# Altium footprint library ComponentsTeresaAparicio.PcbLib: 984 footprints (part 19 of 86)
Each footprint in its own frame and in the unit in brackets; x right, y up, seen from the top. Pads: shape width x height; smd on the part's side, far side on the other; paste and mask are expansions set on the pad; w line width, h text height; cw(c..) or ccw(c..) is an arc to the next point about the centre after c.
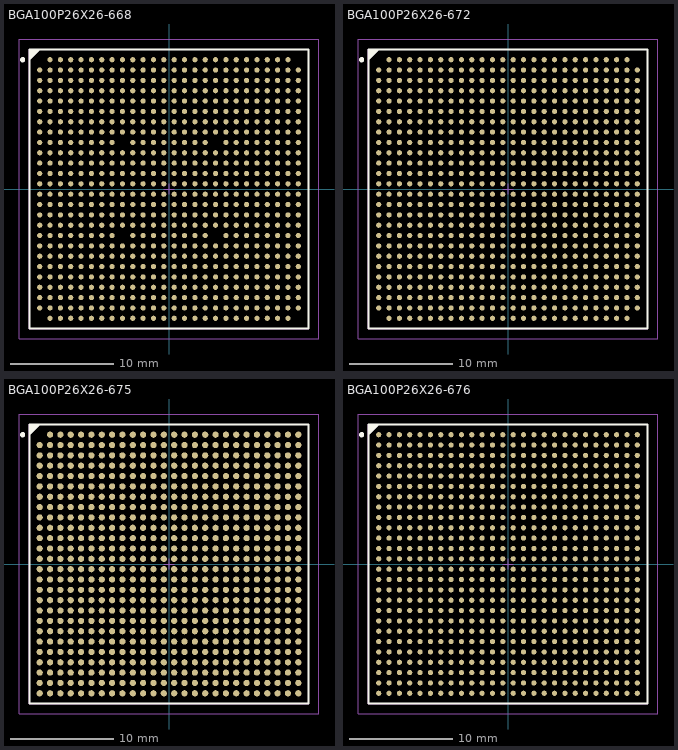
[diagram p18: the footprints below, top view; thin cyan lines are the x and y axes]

## BGA100P26X26-668 [mm] "668-Ball Flip Chip Fine Pitch Ball Grid Array (FF668)"
height 2.85
pads (668):
  round 0.5 smd: A2(-11.5,12.5) A3(-10.5,12.5) A4(-9.5,12.5) A5(-8.5,12.5) A6(-7.5,12.5) A7(-6.5,12.5) A8(-5.5,12.5) A9(-4.5,12.5) A10(-3.5,12.5) A11(-2.5,12.5) A12(-1.5,12.5) A13(-0.5,12.5) A14(0.5,12.5) A15(1.5,12.5) A16(2.5,12.5) A17(3.5,12.5) A18(4.5,12.5) A19(5.5,12.5) A20(6.5,12.5) A21(7.5,12.5) A22(8.5,12.5) A23(9.5,12.5) A24(10.5,12.5) A25(11.5,12.5) AA1(-12.5,-7.5) AA2(-11.5,-7.5) AA3(-10.5,-7.5) AA4(-9.5,-7.5) AA5(-8.5,-7.5) AA6(-7.5,-7.5) AA7(-6.5,-7.5) AA8(-5.5,-7.5) AA9(-4.5,-7.5) AA10(-3.5,-7.5) AA11(-2.5,-7.5) AA12(-1.5,-7.5) AA13(-0.5,-7.5) AA14(0.5,-7.5) AA15(1.5,-7.5) AA16(2.5,-7.5) AA17(3.5,-7.5) AA18(4.5,-7.5) AA19(5.5,-7.5) AA20(6.5,-7.5) AA21(7.5,-7.5) AA22(8.5,-7.5) AA23(9.5,-7.5) AA24(10.5,-7.5) AA25(11.5,-7.5) AA26(12.5,-7.5) AB1(-12.5,-8.5) AB2(-11.5,-8.5) AB3(-10.5,-8.5) AB4(-9.5,-8.5) AB5(-8.5,-8.5) AB6(-7.5,-8.5) AB7(-6.5,-8.5) AB8(-5.5,-8.5) AB9(-4.5,-8.5) AB10(-3.5,-8.5) AB11(-2.5,-8.5) AB12(-1.5,-8.5) AB13(-0.5,-8.5) AB14(0.5,-8.5) AB15(1.5,-8.5) AB16(2.5,-8.5) AB17(3.5,-8.5) AB18(4.5,-8.5) AB19(5.5,-8.5) AB20(6.5,-8.5) AB21(7.5,-8.5) AB22(8.5,-8.5) AB23(9.5,-8.5) AB24(10.5,-8.5) AB25(11.5,-8.5) AB26(12.5,-8.5) AC1(-12.5,-9.5) AC2(-11.5,-9.5) AC3(-10.5,-9.5) AC4(-9.5,-9.5) AC5(-8.5,-9.5) AC6(-7.5,-9.5) AC7(-6.5,-9.5) AC8(-5.5,-9.5) AC9(-4.5,-9.5) AC10(-3.5,-9.5) AC11(-2.5,-9.5) AC12(-1.5,-9.5) AC13(-0.5,-9.5) AC14(0.5,-9.5) AC15(1.5,-9.5) AC16(2.5,-9.5) AC17(3.5,-9.5) AC18(4.5,-9.5) AC19(5.5,-9.5) AC20(6.5,-9.5) AC21(7.5,-9.5) AC22(8.5,-9.5) AC23(9.5,-9.5) AC24(10.5,-9.5) AC25(11.5,-9.5) AC26(12.5,-9.5) AD1(-12.5,-10.5) AD2(-11.5,-10.5) AD3(-10.5,-10.5) AD4(-9.5,-10.5) AD5(-8.5,-10.5) AD6(-7.5,-10.5) AD7(-6.5,-10.5) AD8(-5.5,-10.5) AD9(-4.5,-10.5) AD10(-3.5,-10.5) AD11(-2.5,-10.5) AD12(-1.5,-10.5) AD13(-0.5,-10.5) AD14(0.5,-10.5) AD15(1.5,-10.5) AD16(2.5,-10.5) AD17(3.5,-10.5) AD18(4.5,-10.5) AD19(5.5,-10.5) AD20(6.5,-10.5) AD21(7.5,-10.5) AD22(8.5,-10.5) AD23(9.5,-10.5) AD24(10.5,-10.5) AD25(11.5,-10.5) AD26(12.5,-10.5) AE1(-12.5,-11.5) AE2(-11.5,-11.5) AE3(-10.5,-11.5) AE4(-9.5,-11.5) AE5(-8.5,-11.5) AE6(-7.5,-11.5) AE7(-6.5,-11.5) AE8(-5.5,-11.5) AE9(-4.5,-11.5) AE10(-3.5,-11.5) AE11(-2.5,-11.5) AE12(-1.5,-11.5) AE13(-0.5,-11.5) AE14(0.5,-11.5) AE15(1.5,-11.5) AE16(2.5,-11.5) AE17(3.5,-11.5) AE18(4.5,-11.5) AE19(5.5,-11.5) AE20(6.5,-11.5) AE21(7.5,-11.5) AE22(8.5,-11.5) AE23(9.5,-11.5) AE24(10.5,-11.5) AE25(11.5,-11.5) AE26(12.5,-11.5) AF2(-11.5,-12.5) AF3(-10.5,-12.5) AF4(-9.5,-12.5) AF5(-8.5,-12.5) AF6(-7.5,-12.5) AF7(-6.5,-12.5) AF8(-5.5,-12.5) AF9(-4.5,-12.5) AF10(-3.5,-12.5) AF11(-2.5,-12.5) AF12(-1.5,-12.5) AF13(-0.5,-12.5) AF14(0.5,-12.5) AF15(1.5,-12.5) AF16(2.5,-12.5) AF17(3.5,-12.5) AF18(4.5,-12.5) AF19(5.5,-12.5) AF20(6.5,-12.5) AF21(7.5,-12.5) AF22(8.5,-12.5) AF23(9.5,-12.5) AF24(10.5,-12.5) AF25(11.5,-12.5) B1(-12.5,11.5) B2(-11.5,11.5) B3(-10.5,11.5) B4(-9.5,11.5) B5(-8.5,11.5) B6(-7.5,11.5) B7(-6.5,11.5) B8(-5.5,11.5) B9(-4.5,11.5) B10(-3.5,11.5) B11(-2.5,11.5) B12(-1.5,11.5) B13(-0.5,11.5) B14(0.5,11.5) B15(1.5,11.5) B16(2.5,11.5) B17(3.5,11.5) B18(4.5,11.5) B19(5.5,11.5) B20(6.5,11.5) B21(7.5,11.5) B22(8.5,11.5) B23(9.5,11.5) B24(10.5,11.5) B25(11.5,11.5) B26(12.5,11.5) C1(-12.5,10.5) C2(-11.5,10.5) C3(-10.5,10.5) C4(-9.5,10.5) C5(-8.5,10.5) C6(-7.5,10.5) C7(-6.5,10.5) C8(-5.5,10.5) C9(-4.5,10.5) C10(-3.5,10.5) C11(-2.5,10.5) C12(-1.5,10.5) C13(-0.5,10.5) C14(0.5,10.5) C15(1.5,10.5) C16(2.5,10.5) C17(3.5,10.5) C18(4.5,10.5) C19(5.5,10.5) C20(6.5,10.5) C21(7.5,10.5) C22(8.5,10.5) C23(9.5,10.5) C24(10.5,10.5) C25(11.5,10.5) C26(12.5,10.5) D1(-12.5,9.5) D2(-11.5,9.5) D3(-10.5,9.5) D4(-9.5,9.5) D5(-8.5,9.5) D6(-7.5,9.5) D7(-6.5,9.5) D8(-5.5,9.5) D9(-4.5,9.5) D10(-3.5,9.5) D11(-2.5,9.5) D12(-1.5,9.5) D13(-0.5,9.5) D14(0.5,9.5) D15(1.5,9.5) D16(2.5,9.5) D17(3.5,9.5) D18(4.5,9.5) D19(5.5,9.5) D20(6.5,9.5) D21(7.5,9.5) D22(8.5,9.5) D23(9.5,9.5) D24(10.5,9.5) D25(11.5,9.5) D26(12.5,9.5) E1(-12.5,8.5) E2(-11.5,8.5) E3(-10.5,8.5) E4(-9.5,8.5) E5(-8.5,8.5) E6(-7.5,8.5) E7(-6.5,8.5) E8(-5.5,8.5) E9(-4.5,8.5) E10(-3.5,8.5) E11(-2.5,8.5) E12(-1.5,8.5) E13(-0.5,8.5) E14(0.5,8.5) E15(1.5,8.5) E16(2.5,8.5) E17(3.5,8.5) E18(4.5,8.5) E19(5.5,8.5) E20(6.5,8.5) E21(7.5,8.5) E22(8.5,8.5) E23(9.5,8.5) E24(10.5,8.5) E25(11.5,8.5) E26(12.5,8.5) F1(-12.5,7.5) F2(-11.5,7.5) F3(-10.5,7.5) F4(-9.5,7.5) F5(-8.5,7.5) F6(-7.5,7.5) F7(-6.5,7.5) F8(-5.5,7.5) F9(-4.5,7.5) F10(-3.5,7.5) F11(-2.5,7.5) F12(-1.5,7.5) F13(-0.5,7.5) F14(0.5,7.5) F15(1.5,7.5) F16(2.5,7.5) F17(3.5,7.5) F18(4.5,7.5) F19(5.5,7.5) F20(6.5,7.5) F21(7.5,7.5) F22(8.5,7.5) F23(9.5,7.5) F24(10.5,7.5) F25(11.5,7.5) F26(12.5,7.5) G1(-12.5,6.5) G2(-11.5,6.5) G3(-10.5,6.5) G4(-9.5,6.5) G5(-8.5,6.5) G6(-7.5,6.5) G7(-6.5,6.5) G8(-5.5,6.5) G9(-4.5,6.5) G10(-3.5,6.5) G11(-2.5,6.5) G12(-1.5,6.5) G13(-0.5,6.5) G14(0.5,6.5) G15(1.5,6.5) G16(2.5,6.5) G17(3.5,6.5) G18(4.5,6.5) G19(5.5,6.5) G20(6.5,6.5) G21(7.5,6.5) G22(8.5,6.5) G23(9.5,6.5) G24(10.5,6.5) G25(11.5,6.5) G26(12.5,6.5) H1(-12.5,5.5) H2(-11.5,5.5) H3(-10.5,5.5) H4(-9.5,5.5) H5(-8.5,5.5) H6(-7.5,5.5) H7(-6.5,5.5) H8(-5.5,5.5) H9(-4.5,5.5) H10(-3.5,5.5) H11(-2.5,5.5) H12(-1.5,5.5) H13(-0.5,5.5) H14(0.5,5.5) H15(1.5,5.5) H16(2.5,5.5) H17(3.5,5.5) H18(4.5,5.5) H19(5.5,5.5) H20(6.5,5.5) H21(7.5,5.5) H22(8.5,5.5) H23(9.5,5.5) H24(10.5,5.5) H25(11.5,5.5) H26(12.5,5.5) J1(-12.5,4.5) J2(-11.5,4.5) J3(-10.5,4.5) J4(-9.5,4.5) J5(-8.5,4.5) J6(-7.5,4.5) J7(-6.5,4.5) J8(-5.5,4.5) J10(-3.5,4.5) J11(-2.5,4.5) J12(-1.5,4.5) J13(-0.5,4.5) J14(0.5,4.5) J15(1.5,4.5) J16(2.5,4.5) J17(3.5,4.5) J19(5.5,4.5) J20(6.5,4.5) J21(7.5,4.5) J22(8.5,4.5) J23(9.5,4.5) J24(10.5,4.5) J25(11.5,4.5) J26(12.5,4.5) K1(-12.5,3.5) K2(-11.5,3.5) K3(-10.5,3.5) K4(-9.5,3.5) K5(-8.5,3.5) K6(-7.5,3.5) K7(-6.5,3.5) K8(-5.5,3.5) K9(-4.5,3.5) K10(-3.5,3.5) K11(-2.5,3.5) K12(-1.5,3.5) K13(-0.5,3.5) K14(0.5,3.5) K15(1.5,3.5) K16(2.5,3.5) K17(3.5,3.5) K18(4.5,3.5) K19(5.5,3.5) K20(6.5,3.5) K21(7.5,3.5) K22(8.5,3.5) K23(9.5,3.5) K24(10.5,3.5) K25(11.5,3.5) K26(12.5,3.5) L1(-12.5,2.5) L2(-11.5,2.5) L3(-10.5,2.5) L4(-9.5,2.5) L5(-8.5,2.5) L6(-7.5,2.5) L7(-6.5,2.5) L8(-5.5,2.5) L9(-4.5,2.5) L10(-3.5,2.5) L11(-2.5,2.5) L12(-1.5,2.5) L13(-0.5,2.5) L14(0.5,2.5) L15(1.5,2.5) L16(2.5,2.5) L17(3.5,2.5) L18(4.5,2.5) L19(5.5,2.5) L20(6.5,2.5) L21(7.5,2.5) L22(8.5,2.5) L23(9.5,2.5) L24(10.5,2.5) L25(11.5,2.5) L26(12.5,2.5) M1(-12.5,1.5) M2(-11.5,1.5) M3(-10.5,1.5) M4(-9.5,1.5) M5(-8.5,1.5) M6(-7.5,1.5) M7(-6.5,1.5) M8(-5.5,1.5) M9(-4.5,1.5) M10(-3.5,1.5) M11(-2.5,1.5) M12(-1.5,1.5) M13(-0.5,1.5) M14(0.5,1.5) M15(1.5,1.5) M16(2.5,1.5) M17(3.5,1.5) M18(4.5,1.5) M19(5.5,1.5) M20(6.5,1.5) M21(7.5,1.5) M22(8.5,1.5) M23(9.5,1.5) M24(10.5,1.5) M25(11.5,1.5) M26(12.5,1.5) N1(-12.5,0.5) N2(-11.5,0.5) N3(-10.5,0.5) N4(-9.5,0.5) N5(-8.5,0.5) N6(-7.5,0.5) N7(-6.5,0.5) N8(-5.5,0.5) N9(-4.5,0.5) N10(-3.5,0.5) N11(-2.5,0.5) N12(-1.5,0.5) N13(-0.5,0.5) N14(0.5,0.5) N15(1.5,0.5) N16(2.5,0.5) N17(3.5,0.5) N18(4.5,0.5) N19(5.5,0.5) N20(6.5,0.5) N21(7.5,0.5) N22(8.5,0.5) N23(9.5,0.5) N24(10.5,0.5) N25(11.5,0.5) N26(12.5,0.5) P1(-12.5,-0.5) P2(-11.5,-0.5) P3(-10.5,-0.5) P4(-9.5,-0.5) P5(-8.5,-0.5) P6(-7.5,-0.5) P7(-6.5,-0.5) P8(-5.5,-0.5) P9(-4.5,-0.5) P10(-3.5,-0.5) P11(-2.5,-0.5) P12(-1.5,-0.5) P13(-0.5,-0.5) P14(0.5,-0.5) P15(1.5,-0.5) P16(2.5,-0.5) P17(3.5,-0.5) P18(4.5,-0.5) P19(5.5,-0.5) P20(6.5,-0.5) P21(7.5,-0.5) P22(8.5,-0.5) P23(9.5,-0.5) P24(10.5,-0.5) P25(11.5,-0.5) P26(12.5,-0.5) R1(-12.5,-1.5) R2(-11.5,-1.5) R3(-10.5,-1.5) R4(-9.5,-1.5) R5(-8.5,-1.5) R6(-7.5,-1.5) R7(-6.5,-1.5) R8(-5.5,-1.5) R9(-4.5,-1.5) R10(-3.5,-1.5) R11(-2.5,-1.5) R12(-1.5,-1.5) R13(-0.5,-1.5) R14(0.5,-1.5) R15(1.5,-1.5) R16(2.5,-1.5) R17(3.5,-1.5) R18(4.5,-1.5) R19(5.5,-1.5) R20(6.5,-1.5) R21(7.5,-1.5) R22(8.5,-1.5) R23(9.5,-1.5) R24(10.5,-1.5) R25(11.5,-1.5) R26(12.5,-1.5) T1(-12.5,-2.5) T2(-11.5,-2.5) T3(-10.5,-2.5) T4(-9.5,-2.5) T5(-8.5,-2.5) T6(-7.5,-2.5) T7(-6.5,-2.5) T8(-5.5,-2.5) T9(-4.5,-2.5) T10(-3.5,-2.5) T11(-2.5,-2.5) T12(-1.5,-2.5) T13(-0.5,-2.5) T14(0.5,-2.5) T15(1.5,-2.5) T16(2.5,-2.5) T17(3.5,-2.5) T18(4.5,-2.5) T19(5.5,-2.5) T20(6.5,-2.5) T21(7.5,-2.5) T22(8.5,-2.5) T23(9.5,-2.5) T24(10.5,-2.5) T25(11.5,-2.5) T26(12.5,-2.5) U1(-12.5,-3.5) U2(-11.5,-3.5) U3(-10.5,-3.5) U4(-9.5,-3.5) U5(-8.5,-3.5) U6(-7.5,-3.5) U7(-6.5,-3.5) U8(-5.5,-3.5) U9(-4.5,-3.5) U10(-3.5,-3.5) U11(-2.5,-3.5) U12(-1.5,-3.5) U13(-0.5,-3.5) U14(0.5,-3.5) U15(1.5,-3.5) U16(2.5,-3.5) U17(3.5,-3.5) U18(4.5,-3.5) U19(5.5,-3.5) U20(6.5,-3.5) U21(7.5,-3.5) U22(8.5,-3.5) U23(9.5,-3.5) U24(10.5,-3.5) U25(11.5,-3.5) U26(12.5,-3.5) V1(-12.5,-4.5) V2(-11.5,-4.5) V3(-10.5,-4.5) V4(-9.5,-4.5) V5(-8.5,-4.5) V6(-7.5,-4.5) V7(-6.5,-4.5) V8(-5.5,-4.5) V10(-3.5,-4.5) V11(-2.5,-4.5) V12(-1.5,-4.5) V13(-0.5,-4.5) V14(0.5,-4.5) V15(1.5,-4.5) V16(2.5,-4.5) V17(3.5,-4.5) V19(5.5,-4.5) V20(6.5,-4.5) V21(7.5,-4.5) V22(8.5,-4.5) V23(9.5,-4.5) V24(10.5,-4.5) V25(11.5,-4.5) V26(12.5,-4.5) W1(-12.5,-5.5) W2(-11.5,-5.5) W3(-10.5,-5.5) W4(-9.5,-5.5) W5(-8.5,-5.5) W6(-7.5,-5.5) W7(-6.5,-5.5) W8(-5.5,-5.5) W9(-4.5,-5.5) W10(-3.5,-5.5) W11(-2.5,-5.5) W12(-1.5,-5.5) W13(-0.5,-5.5) W14(0.5,-5.5) W15(1.5,-5.5) W16(2.5,-5.5) W17(3.5,-5.5) W18(4.5,-5.5) W19(5.5,-5.5) W20(6.5,-5.5) W21(7.5,-5.5) W22(8.5,-5.5) W23(9.5,-5.5) W24(10.5,-5.5) W25(11.5,-5.5) W26(12.5,-5.5) Y1(-12.5,-6.5) Y2(-11.5,-6.5) Y3(-10.5,-6.5) Y4(-9.5,-6.5) Y5(-8.5,-6.5) Y6(-7.5,-6.5) Y7(-6.5,-6.5) Y8(-5.5,-6.5) Y9(-4.5,-6.5) Y10(-3.5,-6.5) Y11(-2.5,-6.5) Y12(-1.5,-6.5) Y13(-0.5,-6.5) Y14(0.5,-6.5) Y15(1.5,-6.5) Y16(2.5,-6.5) Y17(3.5,-6.5) Y18(4.5,-6.5) Y19(5.5,-6.5) Y20(6.5,-6.5) Y21(7.5,-6.5) Y22(8.5,-6.5) Y23(9.5,-6.5) Y24(10.5,-6.5) Y25(11.5,-6.5) Y26(12.5,-6.5)
Top Overlay:
  circle w0.25: c-14.15,12.5 r0.125
  region: -12.5,13.5 -13.5,12.5 -13.5,13.5
  lines w0.2: -13.5,12.5 -12.5,13.5 ; -13.5,-13.5 13.5,-13.5 13.5,13.5 -13.5,13.5 -13.5,-13.5
Mechanical 13:
  lines w0.1: -13.5,-13.5 13.5,-13.5 13.5,13.5 -13.5,13.5 -13.5,-13.5
Mechanical 15:
  lines w0.1: -0.5,0 0.5,0 ; 0,-0.5 0,0.5 ; -14.5,-14.5 14.5,-14.5 14.5,14.5 -14.5,14.5 -14.5,-14.5
3D body: height 0, standoff 0, extent -13.5,-13.5 13.5,13.5

## BGA100P26X26-672 [mm] "BGA, 672-Leads, Body 27x27mm, Pitch 1mm"
height 3.5
pads (672):
  round 0.5 smd: A2(-11.5,12.5) A3(-10.5,12.5) A4(-9.5,12.5) A5(-8.5,12.5) A6(-7.5,12.5) A7(-6.5,12.5) A8(-5.5,12.5) A9(-4.5,12.5) A10(-3.5,12.5) A11(-2.5,12.5) A12(-1.5,12.5) A13(-0.5,12.5) A14(0.5,12.5) A15(1.5,12.5) A16(2.5,12.5) A17(3.5,12.5) A18(4.5,12.5) A19(5.5,12.5) A20(6.5,12.5) A21(7.5,12.5) A22(8.5,12.5) A23(9.5,12.5) A24(10.5,12.5) A25(11.5,12.5) AA1(-12.5,-7.5) AA2(-11.5,-7.5) AA3(-10.5,-7.5) AA4(-9.5,-7.5) AA5(-8.5,-7.5) AA6(-7.5,-7.5) AA7(-6.5,-7.5) AA8(-5.5,-7.5) AA9(-4.5,-7.5) AA10(-3.5,-7.5) AA11(-2.5,-7.5) AA12(-1.5,-7.5) AA13(-0.5,-7.5) AA14(0.5,-7.5) AA15(1.5,-7.5) AA16(2.5,-7.5) AA17(3.5,-7.5) AA18(4.5,-7.5) AA19(5.5,-7.5) AA20(6.5,-7.5) AA21(7.5,-7.5) AA22(8.5,-7.5) AA23(9.5,-7.5) AA24(10.5,-7.5) AA25(11.5,-7.5) AA26(12.5,-7.5) AB1(-12.5,-8.5) AB2(-11.5,-8.5) AB3(-10.5,-8.5) AB4(-9.5,-8.5) AB5(-8.5,-8.5) AB6(-7.5,-8.5) AB7(-6.5,-8.5) AB8(-5.5,-8.5) AB9(-4.5,-8.5) AB10(-3.5,-8.5) AB11(-2.5,-8.5) AB12(-1.5,-8.5) AB13(-0.5,-8.5) AB14(0.5,-8.5) AB15(1.5,-8.5) AB16(2.5,-8.5) AB17(3.5,-8.5) AB18(4.5,-8.5) AB19(5.5,-8.5) AB20(6.5,-8.5) AB21(7.5,-8.5) AB22(8.5,-8.5) AB23(9.5,-8.5) AB24(10.5,-8.5) AB25(11.5,-8.5) AB26(12.5,-8.5) AC1(-12.5,-9.5) AC2(-11.5,-9.5) AC3(-10.5,-9.5) AC4(-9.5,-9.5) AC5(-8.5,-9.5) AC6(-7.5,-9.5) AC7(-6.5,-9.5) AC8(-5.5,-9.5) AC9(-4.5,-9.5) AC10(-3.5,-9.5) AC11(-2.5,-9.5) AC12(-1.5,-9.5) AC13(-0.5,-9.5) AC14(0.5,-9.5) AC15(1.5,-9.5) AC16(2.5,-9.5) AC17(3.5,-9.5) AC18(4.5,-9.5) AC19(5.5,-9.5) AC20(6.5,-9.5) AC21(7.5,-9.5) AC22(8.5,-9.5) AC23(9.5,-9.5) AC24(10.5,-9.5) AC25(11.5,-9.5) AC26(12.5,-9.5) AD1(-12.5,-10.5) AD2(-11.5,-10.5) AD3(-10.5,-10.5) AD4(-9.5,-10.5) AD5(-8.5,-10.5) AD6(-7.5,-10.5) AD7(-6.5,-10.5) AD8(-5.5,-10.5) AD9(-4.5,-10.5) AD10(-3.5,-10.5) AD11(-2.5,-10.5) AD12(-1.5,-10.5) AD13(-0.5,-10.5) AD14(0.5,-10.5) AD15(1.5,-10.5) AD16(2.5,-10.5) AD17(3.5,-10.5) AD18(4.5,-10.5) AD19(5.5,-10.5) AD20(6.5,-10.5) AD21(7.5,-10.5) AD22(8.5,-10.5) AD23(9.5,-10.5) AD24(10.5,-10.5) AD25(11.5,-10.5) AD26(12.5,-10.5) AE1(-12.5,-11.5) AE2(-11.5,-11.5) AE3(-10.5,-11.5) AE4(-9.5,-11.5) AE5(-8.5,-11.5) AE6(-7.5,-11.5) AE7(-6.5,-11.5) AE8(-5.5,-11.5) AE9(-4.5,-11.5) AE10(-3.5,-11.5) AE11(-2.5,-11.5) AE12(-1.5,-11.5) AE13(-0.5,-11.5) AE14(0.5,-11.5) AE15(1.5,-11.5) AE16(2.5,-11.5) AE17(3.5,-11.5) AE18(4.5,-11.5) AE19(5.5,-11.5) AE20(6.5,-11.5) AE21(7.5,-11.5) AE22(8.5,-11.5) AE23(9.5,-11.5) AE24(10.5,-11.5) AE25(11.5,-11.5) AE26(12.5,-11.5) AF2(-11.5,-12.5) AF3(-10.5,-12.5) AF4(-9.5,-12.5) AF5(-8.5,-12.5) AF6(-7.5,-12.5) AF7(-6.5,-12.5) AF8(-5.5,-12.5) AF9(-4.5,-12.5) AF10(-3.5,-12.5) AF11(-2.5,-12.5) AF12(-1.5,-12.5) AF13(-0.5,-12.5) AF14(0.5,-12.5) AF15(1.5,-12.5) AF16(2.5,-12.5) AF17(3.5,-12.5) AF18(4.5,-12.5) AF19(5.5,-12.5) AF20(6.5,-12.5) AF21(7.5,-12.5) AF22(8.5,-12.5) AF23(9.5,-12.5) AF24(10.5,-12.5) AF25(11.5,-12.5) B1(-12.5,11.5) B2(-11.5,11.5) B3(-10.5,11.5) B4(-9.5,11.5) B5(-8.5,11.5) B6(-7.5,11.5) B7(-6.5,11.5) B8(-5.5,11.5) B9(-4.5,11.5) B10(-3.5,11.5) B11(-2.5,11.5) B12(-1.5,11.5) B13(-0.5,11.5) B14(0.5,11.5) B15(1.5,11.5) B16(2.5,11.5) B17(3.5,11.5) B18(4.5,11.5) B19(5.5,11.5) B20(6.5,11.5) B21(7.5,11.5) B22(8.5,11.5) B23(9.5,11.5) B24(10.5,11.5) B25(11.5,11.5) B26(12.5,11.5) C1(-12.5,10.5) C2(-11.5,10.5) C3(-10.5,10.5) C4(-9.5,10.5) C5(-8.5,10.5) C6(-7.5,10.5) C7(-6.5,10.5) C8(-5.5,10.5) C9(-4.5,10.5) C10(-3.5,10.5) C11(-2.5,10.5) C12(-1.5,10.5) C13(-0.5,10.5) C14(0.5,10.5) C15(1.5,10.5) C16(2.5,10.5) C17(3.5,10.5) C18(4.5,10.5) C19(5.5,10.5) C20(6.5,10.5) C21(7.5,10.5) C22(8.5,10.5) C23(9.5,10.5) C24(10.5,10.5) C25(11.5,10.5) C26(12.5,10.5) D1(-12.5,9.5) D2(-11.5,9.5) D3(-10.5,9.5) D4(-9.5,9.5) D5(-8.5,9.5) D6(-7.5,9.5) D7(-6.5,9.5) D8(-5.5,9.5) D9(-4.5,9.5) D10(-3.5,9.5) D11(-2.5,9.5) D12(-1.5,9.5) D13(-0.5,9.5) D14(0.5,9.5) D15(1.5,9.5) D16(2.5,9.5) D17(3.5,9.5) D18(4.5,9.5) D19(5.5,9.5) D20(6.5,9.5) D21(7.5,9.5) D22(8.5,9.5) D23(9.5,9.5) D24(10.5,9.5) D25(11.5,9.5) D26(12.5,9.5) E1(-12.5,8.5) E2(-11.5,8.5) E3(-10.5,8.5) E4(-9.5,8.5) E5(-8.5,8.5) E6(-7.5,8.5) E7(-6.5,8.5) E8(-5.5,8.5) E9(-4.5,8.5) E10(-3.5,8.5) E11(-2.5,8.5) E12(-1.5,8.5) E13(-0.5,8.5) E14(0.5,8.5) E15(1.5,8.5) E16(2.5,8.5) E17(3.5,8.5) E18(4.5,8.5) E19(5.5,8.5) E20(6.5,8.5) E21(7.5,8.5) E22(8.5,8.5) E23(9.5,8.5) E24(10.5,8.5) E25(11.5,8.5) E26(12.5,8.5) F1(-12.5,7.5) F2(-11.5,7.5) F3(-10.5,7.5) F4(-9.5,7.5) F5(-8.5,7.5) F6(-7.5,7.5) F7(-6.5,7.5) F8(-5.5,7.5) F9(-4.5,7.5) F10(-3.5,7.5) F11(-2.5,7.5) F12(-1.5,7.5) F13(-0.5,7.5) F14(0.5,7.5) F15(1.5,7.5) F16(2.5,7.5) F17(3.5,7.5) F18(4.5,7.5) F19(5.5,7.5) F20(6.5,7.5) F21(7.5,7.5) F22(8.5,7.5) F23(9.5,7.5) F24(10.5,7.5) F25(11.5,7.5) F26(12.5,7.5) G1(-12.5,6.5) G2(-11.5,6.5) G3(-10.5,6.5) G4(-9.5,6.5) G5(-8.5,6.5) G6(-7.5,6.5) G7(-6.5,6.5) G8(-5.5,6.5) G9(-4.5,6.5) G10(-3.5,6.5) G11(-2.5,6.5) G12(-1.5,6.5) G13(-0.5,6.5) G14(0.5,6.5) G15(1.5,6.5) G16(2.5,6.5) G17(3.5,6.5) G18(4.5,6.5) G19(5.5,6.5) G20(6.5,6.5) G21(7.5,6.5) G22(8.5,6.5) G23(9.5,6.5) G24(10.5,6.5) G25(11.5,6.5) G26(12.5,6.5) H1(-12.5,5.5) H2(-11.5,5.5) H3(-10.5,5.5) H4(-9.5,5.5) H5(-8.5,5.5) H6(-7.5,5.5) H7(-6.5,5.5) H8(-5.5,5.5) H9(-4.5,5.5) H10(-3.5,5.5) H11(-2.5,5.5) H12(-1.5,5.5) H13(-0.5,5.5) H14(0.5,5.5) H15(1.5,5.5) H16(2.5,5.5) H17(3.5,5.5) H18(4.5,5.5) H19(5.5,5.5) H20(6.5,5.5) H21(7.5,5.5) H22(8.5,5.5) H23(9.5,5.5) H24(10.5,5.5) H25(11.5,5.5) H26(12.5,5.5) J1(-12.5,4.5) J2(-11.5,4.5) J3(-10.5,4.5) J4(-9.5,4.5) J5(-8.5,4.5) J6(-7.5,4.5) J7(-6.5,4.5) J8(-5.5,4.5) J9(-4.5,4.5) J10(-3.5,4.5) J11(-2.5,4.5) J12(-1.5,4.5) J13(-0.5,4.5) J14(0.5,4.5) J15(1.5,4.5) J16(2.5,4.5) J17(3.5,4.5) J18(4.5,4.5) J19(5.5,4.5) J20(6.5,4.5) J21(7.5,4.5) J22(8.5,4.5) J23(9.5,4.5) J24(10.5,4.5) J25(11.5,4.5) J26(12.5,4.5) K1(-12.5,3.5) K2(-11.5,3.5) K3(-10.5,3.5) K4(-9.5,3.5) K5(-8.5,3.5) K6(-7.5,3.5) K7(-6.5,3.5) K8(-5.5,3.5) K9(-4.5,3.5) K10(-3.5,3.5) K11(-2.5,3.5) K12(-1.5,3.5) K13(-0.5,3.5) K14(0.5,3.5) K15(1.5,3.5) K16(2.5,3.5) K17(3.5,3.5) K18(4.5,3.5) K19(5.5,3.5) K20(6.5,3.5) K21(7.5,3.5) K22(8.5,3.5) K23(9.5,3.5) K24(10.5,3.5) K25(11.5,3.5) K26(12.5,3.5) L1(-12.5,2.5) L2(-11.5,2.5) L3(-10.5,2.5) L4(-9.5,2.5) L5(-8.5,2.5) L6(-7.5,2.5) L7(-6.5,2.5) L8(-5.5,2.5) L9(-4.5,2.5) L10(-3.5,2.5) L11(-2.5,2.5) L12(-1.5,2.5) L13(-0.5,2.5) L14(0.5,2.5) L15(1.5,2.5) L16(2.5,2.5) L17(3.5,2.5) L18(4.5,2.5) L19(5.5,2.5) L20(6.5,2.5) L21(7.5,2.5) L22(8.5,2.5) L23(9.5,2.5) L24(10.5,2.5) L25(11.5,2.5) L26(12.5,2.5) M1(-12.5,1.5) M2(-11.5,1.5) M3(-10.5,1.5) M4(-9.5,1.5) M5(-8.5,1.5) M6(-7.5,1.5) M7(-6.5,1.5) M8(-5.5,1.5) M9(-4.5,1.5) M10(-3.5,1.5) M11(-2.5,1.5) M12(-1.5,1.5) M13(-0.5,1.5) M14(0.5,1.5) M15(1.5,1.5) M16(2.5,1.5) M17(3.5,1.5) M18(4.5,1.5) M19(5.5,1.5) M20(6.5,1.5) M21(7.5,1.5) M22(8.5,1.5) M23(9.5,1.5) M24(10.5,1.5) M25(11.5,1.5) M26(12.5,1.5) N1(-12.5,0.5) N2(-11.5,0.5) N3(-10.5,0.5) N4(-9.5,0.5) N5(-8.5,0.5) N6(-7.5,0.5) N7(-6.5,0.5) N8(-5.5,0.5) N9(-4.5,0.5) N10(-3.5,0.5) N11(-2.5,0.5) N12(-1.5,0.5) N13(-0.5,0.5) N14(0.5,0.5) N15(1.5,0.5) N16(2.5,0.5) N17(3.5,0.5) N18(4.5,0.5) N19(5.5,0.5) N20(6.5,0.5) N21(7.5,0.5) N22(8.5,0.5) N23(9.5,0.5) N24(10.5,0.5) N25(11.5,0.5) N26(12.5,0.5) P1(-12.5,-0.5) P2(-11.5,-0.5) P3(-10.5,-0.5) P4(-9.5,-0.5) P5(-8.5,-0.5) P6(-7.5,-0.5) P7(-6.5,-0.5) P8(-5.5,-0.5) P9(-4.5,-0.5) P10(-3.5,-0.5) P11(-2.5,-0.5) P12(-1.5,-0.5) P13(-0.5,-0.5) P14(0.5,-0.5) P15(1.5,-0.5) P16(2.5,-0.5) P17(3.5,-0.5) P18(4.5,-0.5) P19(5.5,-0.5) P20(6.5,-0.5) P21(7.5,-0.5) P22(8.5,-0.5) P23(9.5,-0.5) P24(10.5,-0.5) P25(11.5,-0.5) P26(12.5,-0.5) R1(-12.5,-1.5) R2(-11.5,-1.5) R3(-10.5,-1.5) R4(-9.5,-1.5) R5(-8.5,-1.5) R6(-7.5,-1.5) R7(-6.5,-1.5) R8(-5.5,-1.5) R9(-4.5,-1.5) R10(-3.5,-1.5) R11(-2.5,-1.5) R12(-1.5,-1.5) R13(-0.5,-1.5) R14(0.5,-1.5) R15(1.5,-1.5) R16(2.5,-1.5) R17(3.5,-1.5) R18(4.5,-1.5) R19(5.5,-1.5) R20(6.5,-1.5) R21(7.5,-1.5) R22(8.5,-1.5) R23(9.5,-1.5) R24(10.5,-1.5) R25(11.5,-1.5) R26(12.5,-1.5) T1(-12.5,-2.5) T2(-11.5,-2.5) T3(-10.5,-2.5) T4(-9.5,-2.5) T5(-8.5,-2.5) T6(-7.5,-2.5) T7(-6.5,-2.5) T8(-5.5,-2.5) T9(-4.5,-2.5) T10(-3.5,-2.5) T11(-2.5,-2.5) T12(-1.5,-2.5) T13(-0.5,-2.5) T14(0.5,-2.5) T15(1.5,-2.5) T16(2.5,-2.5) T17(3.5,-2.5) T18(4.5,-2.5) T19(5.5,-2.5) T20(6.5,-2.5) T21(7.5,-2.5) T22(8.5,-2.5) T23(9.5,-2.5) T24(10.5,-2.5) T25(11.5,-2.5) T26(12.5,-2.5) U1(-12.5,-3.5) U2(-11.5,-3.5) U3(-10.5,-3.5) U4(-9.5,-3.5) U5(-8.5,-3.5) U6(-7.5,-3.5) U7(-6.5,-3.5) U8(-5.5,-3.5) U9(-4.5,-3.5) U10(-3.5,-3.5) U11(-2.5,-3.5) U12(-1.5,-3.5) U13(-0.5,-3.5) U14(0.5,-3.5) U15(1.5,-3.5) U16(2.5,-3.5) U17(3.5,-3.5) U18(4.5,-3.5) U19(5.5,-3.5) U20(6.5,-3.5) U21(7.5,-3.5) U22(8.5,-3.5) U23(9.5,-3.5) U24(10.5,-3.5) U25(11.5,-3.5) U26(12.5,-3.5) V1(-12.5,-4.5) V2(-11.5,-4.5) V3(-10.5,-4.5) V4(-9.5,-4.5) V5(-8.5,-4.5) V6(-7.5,-4.5) V7(-6.5,-4.5) V8(-5.5,-4.5) V9(-4.5,-4.5) V10(-3.5,-4.5) V11(-2.5,-4.5) V12(-1.5,-4.5) V13(-0.5,-4.5) V14(0.5,-4.5) V15(1.5,-4.5) V16(2.5,-4.5) V17(3.5,-4.5) V18(4.5,-4.5) V19(5.5,-4.5) V20(6.5,-4.5) V21(7.5,-4.5) V22(8.5,-4.5) V23(9.5,-4.5) V24(10.5,-4.5) V25(11.5,-4.5) V26(12.5,-4.5) W1(-12.5,-5.5) W2(-11.5,-5.5) W3(-10.5,-5.5) W4(-9.5,-5.5) W5(-8.5,-5.5) W6(-7.5,-5.5) W7(-6.5,-5.5) W8(-5.5,-5.5) W9(-4.5,-5.5) W10(-3.5,-5.5) W11(-2.5,-5.5) W12(-1.5,-5.5) W13(-0.5,-5.5) W14(0.5,-5.5) W15(1.5,-5.5) W16(2.5,-5.5) W17(3.5,-5.5) W18(4.5,-5.5) W19(5.5,-5.5) W20(6.5,-5.5) W21(7.5,-5.5) W22(8.5,-5.5) W23(9.5,-5.5) W24(10.5,-5.5) W25(11.5,-5.5) W26(12.5,-5.5) Y1(-12.5,-6.5) Y2(-11.5,-6.5) Y3(-10.5,-6.5) Y4(-9.5,-6.5) Y5(-8.5,-6.5) Y6(-7.5,-6.5) Y7(-6.5,-6.5) Y8(-5.5,-6.5) Y9(-4.5,-6.5) Y10(-3.5,-6.5) Y11(-2.5,-6.5) Y12(-1.5,-6.5) Y13(-0.5,-6.5) Y14(0.5,-6.5) Y15(1.5,-6.5) Y16(2.5,-6.5) Y17(3.5,-6.5) Y18(4.5,-6.5) Y19(5.5,-6.5) Y20(6.5,-6.5) Y21(7.5,-6.5) Y22(8.5,-6.5) Y23(9.5,-6.5) Y24(10.5,-6.5) Y25(11.5,-6.5) Y26(12.5,-6.5)
Top Overlay:
  circle w0.25: c-14.15,12.5 r0.125
  region: -12.5,13.5 -13.5,12.5 -13.5,13.5
  lines w0.2: -13.5,12.5 -12.5,13.5 ; -13.5,-13.5 13.5,-13.5 13.5,13.5 -13.5,13.5 -13.5,-13.5
Mechanical 13:
  lines w0.1: -13.5,-13.5 13.5,-13.5 13.5,13.5 -13.5,13.5 -13.5,-13.5
Mechanical 15:
  lines w0.1: -0.5,0 0.5,0 ; 0,-0.5 0,0.5 ; -14.5,-14.5 14.5,-14.5 14.5,14.5 -14.5,14.5 -14.5,-14.5
3D body: height 0, standoff 0, extent -13.5,-13.5 13.5,13.5

## BGA100P26X26-675 [mm] "BGA, 675-Leads, Body 27x27mm, Pitch 1mm"
height 3.22
pads (675):
  round 0.6 smd: A02(-11.5,12.5) A03(-10.5,12.5) A04(-9.5,12.5) A05(-8.5,12.5) A06(-7.5,12.5) A07(-6.5,12.5) A08(-5.5,12.5) A09(-4.5,12.5) A10(-3.5,12.5) A11(-2.5,12.5) A12(-1.5,12.5) A13(-0.5,12.5) A14(0.5,12.5) A15(1.5,12.5) A16(2.5,12.5) A17(3.5,12.5) A18(4.5,12.5) A19(5.5,12.5) A20(6.5,12.5) A21(7.5,12.5) A22(8.5,12.5) A23(9.5,12.5) A24(10.5,12.5) A25(11.5,12.5) A26(12.5,12.5) AA01(-12.5,-7.5) AA02(-11.5,-7.5) AA03(-10.5,-7.5) AA04(-9.5,-7.5) AA05(-8.5,-7.5) AA06(-7.5,-7.5) AA07(-6.5,-7.5) AA08(-5.5,-7.5) AA09(-4.5,-7.5) AA10(-3.5,-7.5) AA11(-2.5,-7.5) AA12(-1.5,-7.5) AA13(-0.5,-7.5) AA14(0.5,-7.5) AA15(1.5,-7.5) AA16(2.5,-7.5) AA17(3.5,-7.5) AA18(4.5,-7.5) AA19(5.5,-7.5) AA20(6.5,-7.5) AA21(7.5,-7.5) AA22(8.5,-7.5) AA23(9.5,-7.5) AA24(10.5,-7.5) AA25(11.5,-7.5) AA26(12.5,-7.5) AB01(-12.5,-8.5) AB02(-11.5,-8.5) AB03(-10.5,-8.5) AB04(-9.5,-8.5) AB05(-8.5,-8.5) AB06(-7.5,-8.5) AB07(-6.5,-8.5) AB08(-5.5,-8.5) AB09(-4.5,-8.5) AB10(-3.5,-8.5) AB11(-2.5,-8.5) AB12(-1.5,-8.5) AB13(-0.5,-8.5) AB14(0.5,-8.5) AB15(1.5,-8.5) AB16(2.5,-8.5) AB17(3.5,-8.5) AB18(4.5,-8.5) AB19(5.5,-8.5) AB20(6.5,-8.5) AB21(7.5,-8.5) AB22(8.5,-8.5) AB23(9.5,-8.5) AB24(10.5,-8.5) AB25(11.5,-8.5) AB26(12.5,-8.5) AC01(-12.5,-9.5) AC02(-11.5,-9.5) AC03(-10.5,-9.5) AC04(-9.5,-9.5) AC05(-8.5,-9.5) AC06(-7.5,-9.5) AC07(-6.5,-9.5) AC08(-5.5,-9.5) AC09(-4.5,-9.5) AC10(-3.5,-9.5) AC11(-2.5,-9.5) AC12(-1.5,-9.5) AC13(-0.5,-9.5) AC14(0.5,-9.5) AC15(1.5,-9.5) AC16(2.5,-9.5) AC17(3.5,-9.5) AC18(4.5,-9.5) AC19(5.5,-9.5) AC20(6.5,-9.5) AC21(7.5,-9.5) AC22(8.5,-9.5) AC23(9.5,-9.5) AC24(10.5,-9.5) AC25(11.5,-9.5) AC26(12.5,-9.5) AD01(-12.5,-10.5) AD02(-11.5,-10.5) AD03(-10.5,-10.5) AD04(-9.5,-10.5) AD05(-8.5,-10.5) AD06(-7.5,-10.5) AD07(-6.5,-10.5) AD08(-5.5,-10.5) AD09(-4.5,-10.5) AD10(-3.5,-10.5) AD11(-2.5,-10.5) AD12(-1.5,-10.5) AD13(-0.5,-10.5) AD14(0.5,-10.5) AD15(1.5,-10.5) AD16(2.5,-10.5) AD17(3.5,-10.5) AD18(4.5,-10.5) AD19(5.5,-10.5) AD20(6.5,-10.5) AD21(7.5,-10.5) AD22(8.5,-10.5) AD23(9.5,-10.5) AD24(10.5,-10.5) AD25(11.5,-10.5) AD26(12.5,-10.5) AE01(-12.5,-11.5) AE02(-11.5,-11.5) AE03(-10.5,-11.5) AE04(-9.5,-11.5) AE05(-8.5,-11.5) AE06(-7.5,-11.5) AE07(-6.5,-11.5) AE08(-5.5,-11.5) AE09(-4.5,-11.5) AE10(-3.5,-11.5) AE11(-2.5,-11.5) AE12(-1.5,-11.5) AE13(-0.5,-11.5) AE14(0.5,-11.5) AE15(1.5,-11.5) AE16(2.5,-11.5) AE17(3.5,-11.5) AE18(4.5,-11.5) AE19(5.5,-11.5) AE20(6.5,-11.5) AE21(7.5,-11.5) AE22(8.5,-11.5) AE23(9.5,-11.5) AE24(10.5,-11.5) AE25(11.5,-11.5) AE26(12.5,-11.5) AF01(-12.5,-12.5) AF02(-11.5,-12.5) AF03(-10.5,-12.5) AF04(-9.5,-12.5) AF05(-8.5,-12.5) AF06(-7.5,-12.5) AF07(-6.5,-12.5) AF08(-5.5,-12.5) AF09(-4.5,-12.5) AF10(-3.5,-12.5) AF11(-2.5,-12.5) AF12(-1.5,-12.5) AF13(-0.5,-12.5) AF14(0.5,-12.5) AF15(1.5,-12.5) AF16(2.5,-12.5) AF17(3.5,-12.5) AF18(4.5,-12.5) AF19(5.5,-12.5) AF20(6.5,-12.5) AF21(7.5,-12.5) AF22(8.5,-12.5) AF23(9.5,-12.5) AF24(10.5,-12.5) AF25(11.5,-12.5) AF26(12.5,-12.5) B01(-12.5,11.5) B02(-11.5,11.5) B03(-10.5,11.5) B04(-9.5,11.5) B05(-8.5,11.5) B06(-7.5,11.5) B07(-6.5,11.5) B08(-5.5,11.5) B09(-4.5,11.5) B10(-3.5,11.5) B11(-2.5,11.5) B12(-1.5,11.5) B13(-0.5,11.5) B14(0.5,11.5) B15(1.5,11.5) B16(2.5,11.5) B17(3.5,11.5) B18(4.5,11.5) B19(5.5,11.5) B20(6.5,11.5) B21(7.5,11.5) B22(8.5,11.5) B23(9.5,11.5) B24(10.5,11.5) B25(11.5,11.5) B26(12.5,11.5) C01(-12.5,10.5) C02(-11.5,10.5) C03(-10.5,10.5) C04(-9.5,10.5) C05(-8.5,10.5) C06(-7.5,10.5) C07(-6.5,10.5) C08(-5.5,10.5) C09(-4.5,10.5) C10(-3.5,10.5) C11(-2.5,10.5) C12(-1.5,10.5) C13(-0.5,10.5) C14(0.5,10.5) C15(1.5,10.5) C16(2.5,10.5) C17(3.5,10.5) C18(4.5,10.5) C19(5.5,10.5) C20(6.5,10.5) C21(7.5,10.5) C22(8.5,10.5) C23(9.5,10.5) C24(10.5,10.5) C25(11.5,10.5) C26(12.5,10.5) D01(-12.5,9.5) D02(-11.5,9.5) D03(-10.5,9.5) D04(-9.5,9.5) D05(-8.5,9.5) D06(-7.5,9.5) D07(-6.5,9.5) D08(-5.5,9.5) D09(-4.5,9.5) D10(-3.5,9.5) D11(-2.5,9.5) D12(-1.5,9.5) D13(-0.5,9.5) D14(0.5,9.5) D15(1.5,9.5) D16(2.5,9.5) D17(3.5,9.5) D18(4.5,9.5) D19(5.5,9.5) D20(6.5,9.5) D21(7.5,9.5) D22(8.5,9.5) D23(9.5,9.5) D24(10.5,9.5) D25(11.5,9.5) D26(12.5,9.5) E01(-12.5,8.5) E02(-11.5,8.5) E03(-10.5,8.5) E04(-9.5,8.5) E05(-8.5,8.5) E06(-7.5,8.5) E07(-6.5,8.5) E08(-5.5,8.5) E09(-4.5,8.5) E10(-3.5,8.5) E11(-2.5,8.5) E12(-1.5,8.5) E13(-0.5,8.5) E14(0.5,8.5) E15(1.5,8.5) E16(2.5,8.5) E17(3.5,8.5) E18(4.5,8.5) E19(5.5,8.5) E20(6.5,8.5) E21(7.5,8.5) E22(8.5,8.5) E23(9.5,8.5) E24(10.5,8.5) E25(11.5,8.5) E26(12.5,8.5) F01(-12.5,7.5) F02(-11.5,7.5) F03(-10.5,7.5) F04(-9.5,7.5) F05(-8.5,7.5) F06(-7.5,7.5) F07(-6.5,7.5) F08(-5.5,7.5) F09(-4.5,7.5) F10(-3.5,7.5) F11(-2.5,7.5) F12(-1.5,7.5) F13(-0.5,7.5) F14(0.5,7.5) F15(1.5,7.5) F16(2.5,7.5) F17(3.5,7.5) F18(4.5,7.5) F19(5.5,7.5) F20(6.5,7.5) F21(7.5,7.5) F22(8.5,7.5) F23(9.5,7.5) F24(10.5,7.5) F25(11.5,7.5) F26(12.5,7.5) G01(-12.5,6.5) G02(-11.5,6.5) G03(-10.5,6.5) G04(-9.5,6.5) G05(-8.5,6.5) G06(-7.5,6.5) G07(-6.5,6.5) G08(-5.5,6.5) G09(-4.5,6.5) G10(-3.5,6.5) G11(-2.5,6.5) G12(-1.5,6.5) G13(-0.5,6.5) G14(0.5,6.5) G15(1.5,6.5) G16(2.5,6.5) G17(3.5,6.5) G18(4.5,6.5) G19(5.5,6.5) G20(6.5,6.5) G21(7.5,6.5) G22(8.5,6.5) G23(9.5,6.5) G24(10.5,6.5) G25(11.5,6.5) G26(12.5,6.5) H01(-12.5,5.5) H02(-11.5,5.5) H03(-10.5,5.5) H04(-9.5,5.5) H05(-8.5,5.5) H06(-7.5,5.5) H07(-6.5,5.5) H08(-5.5,5.5) H09(-4.5,5.5) H10(-3.5,5.5) H11(-2.5,5.5) H12(-1.5,5.5) H13(-0.5,5.5) H14(0.5,5.5) H15(1.5,5.5) H16(2.5,5.5) H17(3.5,5.5) H18(4.5,5.5) H19(5.5,5.5) H20(6.5,5.5) H21(7.5,5.5) H22(8.5,5.5) H23(9.5,5.5) H24(10.5,5.5) H25(11.5,5.5) H26(12.5,5.5) J01(-12.5,4.5) J02(-11.5,4.5) J03(-10.5,4.5) J04(-9.5,4.5) J05(-8.5,4.5) J06(-7.5,4.5) J07(-6.5,4.5) J08(-5.5,4.5) J09(-4.5,4.5) J10(-3.5,4.5) J11(-2.5,4.5) J12(-1.5,4.5) J13(-0.5,4.5) J14(0.5,4.5) J15(1.5,4.5) J16(2.5,4.5) J17(3.5,4.5) J18(4.5,4.5) J19(5.5,4.5) J20(6.5,4.5) J21(7.5,4.5) J22(8.5,4.5) J23(9.5,4.5) J24(10.5,4.5) J25(11.5,4.5) J26(12.5,4.5) K01(-12.5,3.5) K02(-11.5,3.5) K03(-10.5,3.5) K04(-9.5,3.5) K05(-8.5,3.5) K06(-7.5,3.5) K07(-6.5,3.5) K08(-5.5,3.5) K09(-4.5,3.5) K10(-3.5,3.5) K11(-2.5,3.5) K12(-1.5,3.5) K13(-0.5,3.5) K14(0.5,3.5) K15(1.5,3.5) K16(2.5,3.5) K17(3.5,3.5) K18(4.5,3.5) K19(5.5,3.5) K20(6.5,3.5) K21(7.5,3.5) K22(8.5,3.5) K23(9.5,3.5) K24(10.5,3.5) K25(11.5,3.5) K26(12.5,3.5) L01(-12.5,2.5) L02(-11.5,2.5) L03(-10.5,2.5) L04(-9.5,2.5) L05(-8.5,2.5) L06(-7.5,2.5) L07(-6.5,2.5) L08(-5.5,2.5) L09(-4.5,2.5) L10(-3.5,2.5) L11(-2.5,2.5) L12(-1.5,2.5) L13(-0.5,2.5) L14(0.5,2.5) L15(1.5,2.5) L16(2.5,2.5) L17(3.5,2.5) L18(4.5,2.5) L19(5.5,2.5) L20(6.5,2.5) L21(7.5,2.5) L22(8.5,2.5) L23(9.5,2.5) L24(10.5,2.5) L25(11.5,2.5) L26(12.5,2.5) M01(-12.5,1.5) M02(-11.5,1.5) M03(-10.5,1.5) M04(-9.5,1.5) M05(-8.5,1.5) M06(-7.5,1.5) M07(-6.5,1.5) M08(-5.5,1.5) M09(-4.5,1.5) M10(-3.5,1.5) M11(-2.5,1.5) M12(-1.5,1.5) M13(-0.5,1.5) M14(0.5,1.5) M15(1.5,1.5) M16(2.5,1.5) M17(3.5,1.5) M18(4.5,1.5) M19(5.5,1.5) M20(6.5,1.5) M21(7.5,1.5) M22(8.5,1.5) M23(9.5,1.5) M24(10.5,1.5) M25(11.5,1.5) M26(12.5,1.5) N01(-12.5,0.5) N02(-11.5,0.5) N03(-10.5,0.5) N04(-9.5,0.5) N05(-8.5,0.5) N06(-7.5,0.5) N07(-6.5,0.5) N08(-5.5,0.5) N09(-4.5,0.5) N10(-3.5,0.5) N11(-2.5,0.5) N12(-1.5,0.5) N13(-0.5,0.5) N14(0.5,0.5) N15(1.5,0.5) N16(2.5,0.5) N17(3.5,0.5) N18(4.5,0.5) N19(5.5,0.5) N20(6.5,0.5) N21(7.5,0.5) N22(8.5,0.5) N23(9.5,0.5) N24(10.5,0.5) N25(11.5,0.5) N26(12.5,0.5) P01(-12.5,-0.5) P02(-11.5,-0.5) P03(-10.5,-0.5) P04(-9.5,-0.5) P05(-8.5,-0.5) P06(-7.5,-0.5) P07(-6.5,-0.5) P08(-5.5,-0.5) P09(-4.5,-0.5) P10(-3.5,-0.5) P11(-2.5,-0.5) P12(-1.5,-0.5) P13(-0.5,-0.5) P14(0.5,-0.5) P15(1.5,-0.5) P16(2.5,-0.5) P17(3.5,-0.5) P18(4.5,-0.5) P19(5.5,-0.5) P20(6.5,-0.5) P21(7.5,-0.5) P22(8.5,-0.5) P23(9.5,-0.5) P24(10.5,-0.5) P25(11.5,-0.5) P26(12.5,-0.5) R01(-12.5,-1.5) R02(-11.5,-1.5) R03(-10.5,-1.5) R04(-9.5,-1.5) R05(-8.5,-1.5) R06(-7.5,-1.5) R07(-6.5,-1.5) R08(-5.5,-1.5) R09(-4.5,-1.5) R10(-3.5,-1.5) R11(-2.5,-1.5) R12(-1.5,-1.5) R13(-0.5,-1.5) R14(0.5,-1.5) R15(1.5,-1.5) R16(2.5,-1.5) R17(3.5,-1.5) R18(4.5,-1.5) R19(5.5,-1.5) R20(6.5,-1.5) R21(7.5,-1.5) R22(8.5,-1.5) R23(9.5,-1.5) R24(10.5,-1.5) R25(11.5,-1.5) R26(12.5,-1.5) T01(-12.5,-2.5) T02(-11.5,-2.5) T03(-10.5,-2.5) T04(-9.5,-2.5) T05(-8.5,-2.5) T06(-7.5,-2.5) T07(-6.5,-2.5) T08(-5.5,-2.5) T09(-4.5,-2.5) T10(-3.5,-2.5) T11(-2.5,-2.5) T12(-1.5,-2.5) T13(-0.5,-2.5) T14(0.5,-2.5) T15(1.5,-2.5) T16(2.5,-2.5) T17(3.5,-2.5) T18(4.5,-2.5) T19(5.5,-2.5) T20(6.5,-2.5) T21(7.5,-2.5) T22(8.5,-2.5) T23(9.5,-2.5) T24(10.5,-2.5) T25(11.5,-2.5) T26(12.5,-2.5) U01(-12.5,-3.5) U02(-11.5,-3.5) U03(-10.5,-3.5) U04(-9.5,-3.5) U05(-8.5,-3.5) U06(-7.5,-3.5) U07(-6.5,-3.5) U08(-5.5,-3.5) U09(-4.5,-3.5) U10(-3.5,-3.5) U11(-2.5,-3.5) U12(-1.5,-3.5) U13(-0.5,-3.5) U14(0.5,-3.5) U15(1.5,-3.5) U16(2.5,-3.5) U17(3.5,-3.5) U18(4.5,-3.5) U19(5.5,-3.5) U20(6.5,-3.5) U21(7.5,-3.5) U22(8.5,-3.5) U23(9.5,-3.5) U24(10.5,-3.5) U25(11.5,-3.5) U26(12.5,-3.5) V01(-12.5,-4.5) V02(-11.5,-4.5) V03(-10.5,-4.5) V04(-9.5,-4.5) V05(-8.5,-4.5) V06(-7.5,-4.5) V07(-6.5,-4.5) V08(-5.5,-4.5) V09(-4.5,-4.5) V10(-3.5,-4.5) V11(-2.5,-4.5) V12(-1.5,-4.5) V13(-0.5,-4.5) V14(0.5,-4.5) V15(1.5,-4.5) V16(2.5,-4.5) V17(3.5,-4.5) V18(4.5,-4.5) V19(5.5,-4.5) V20(6.5,-4.5) V21(7.5,-4.5) V22(8.5,-4.5) V23(9.5,-4.5) V24(10.5,-4.5) V25(11.5,-4.5) V26(12.5,-4.5) W01(-12.5,-5.5) W02(-11.5,-5.5) W03(-10.5,-5.5) W04(-9.5,-5.5) W05(-8.5,-5.5) W06(-7.5,-5.5) W07(-6.5,-5.5) W08(-5.5,-5.5) W09(-4.5,-5.5) W10(-3.5,-5.5) W11(-2.5,-5.5) W12(-1.5,-5.5) W13(-0.5,-5.5) W14(0.5,-5.5) W15(1.5,-5.5) W16(2.5,-5.5) W17(3.5,-5.5) W18(4.5,-5.5) W19(5.5,-5.5) W20(6.5,-5.5) W21(7.5,-5.5) W22(8.5,-5.5) W23(9.5,-5.5) W24(10.5,-5.5) W25(11.5,-5.5) W26(12.5,-5.5) Y01(-12.5,-6.5) Y02(-11.5,-6.5) Y03(-10.5,-6.5) Y04(-9.5,-6.5) Y05(-8.5,-6.5) Y06(-7.5,-6.5) Y07(-6.5,-6.5) Y08(-5.5,-6.5) Y09(-4.5,-6.5) Y10(-3.5,-6.5) Y11(-2.5,-6.5) Y12(-1.5,-6.5) Y13(-0.5,-6.5) Y14(0.5,-6.5) Y15(1.5,-6.5) Y16(2.5,-6.5) Y17(3.5,-6.5) Y18(4.5,-6.5) Y19(5.5,-6.5) Y20(6.5,-6.5) Y21(7.5,-6.5) Y22(8.5,-6.5) Y23(9.5,-6.5) Y24(10.5,-6.5) Y25(11.5,-6.5) Y26(12.5,-6.5)
Top Overlay:
  circle w0.25: c-14.15,12.5 r0.125
  region: -12.5,13.5 -13.5,12.5 -13.5,13.5
  lines w0.2: -13.5,12.5 -12.5,13.5 ; -13.5,-13.5 13.5,-13.5 13.5,13.5 -13.5,13.5 -13.5,-13.5
Mechanical 13:
  lines w0.1: -13.5,-13.5 13.5,-13.5 13.5,13.5 -13.5,13.5 -13.5,-13.5
Mechanical 15:
  lines w0.1: -0.5,0 0.5,0 ; 0,-0.5 0,0.5 ; -14.5,-14.5 14.5,-14.5 14.5,14.5 -14.5,14.5 -14.5,-14.5
3D body: height 0, standoff 0, extent -13.5,-13.5 13.5,13.5

## BGA100P26X26-676 [mm] "BGA, 676-Leads, Body 27x27mm, Pitch 1mm"
height 2.44
pads (676):
  round 0.5 smd: A1(-12.5,12.5) A2(-11.5,12.5) A3(-10.5,12.5) A4(-9.5,12.5) A5(-8.5,12.5) A6(-7.5,12.5) A7(-6.5,12.5) A8(-5.5,12.5) A9(-4.5,12.5) A10(-3.5,12.5) A11(-2.5,12.5) A12(-1.5,12.5) A13(-0.5,12.5) A14(0.5,12.5) A15(1.5,12.5) A16(2.5,12.5) A17(3.5,12.5) A18(4.5,12.5) A19(5.5,12.5) A20(6.5,12.5) A21(7.5,12.5) A22(8.5,12.5) A23(9.5,12.5) A24(10.5,12.5) A25(11.5,12.5) A26(12.5,12.5) AA1(-12.5,-7.5) AA2(-11.5,-7.5) AA3(-10.5,-7.5) AA4(-9.5,-7.5) AA5(-8.5,-7.5) AA6(-7.5,-7.5) AA7(-6.5,-7.5) AA8(-5.5,-7.5) AA9(-4.5,-7.5) AA10(-3.5,-7.5) AA11(-2.5,-7.5) AA12(-1.5,-7.5) AA13(-0.5,-7.5) AA14(0.5,-7.5) AA15(1.5,-7.5) AA16(2.5,-7.5) AA17(3.5,-7.5) AA18(4.5,-7.5) AA19(5.5,-7.5) AA20(6.5,-7.5) AA21(7.5,-7.5) AA22(8.5,-7.5) AA23(9.5,-7.5) AA24(10.5,-7.5) AA25(11.5,-7.5) AA26(12.5,-7.5) AB1(-12.5,-8.5) AB2(-11.5,-8.5) AB3(-10.5,-8.5) AB4(-9.5,-8.5) AB5(-8.5,-8.5) AB6(-7.5,-8.5) AB7(-6.5,-8.5) AB8(-5.5,-8.5) AB9(-4.5,-8.5) AB10(-3.5,-8.5) AB11(-2.5,-8.5) AB12(-1.5,-8.5) AB13(-0.5,-8.5) AB14(0.5,-8.5) AB15(1.5,-8.5) AB16(2.5,-8.5) AB17(3.5,-8.5) AB18(4.5,-8.5) AB19(5.5,-8.5) AB20(6.5,-8.5) AB21(7.5,-8.5) AB22(8.5,-8.5) AB23(9.5,-8.5) AB24(10.5,-8.5) AB25(11.5,-8.5) AB26(12.5,-8.5) AC1(-12.5,-9.5) AC2(-11.5,-9.5) AC3(-10.5,-9.5) AC4(-9.5,-9.5) AC5(-8.5,-9.5) AC6(-7.5,-9.5) AC7(-6.5,-9.5) AC8(-5.5,-9.5) AC9(-4.5,-9.5) AC10(-3.5,-9.5) AC11(-2.5,-9.5) AC12(-1.5,-9.5) AC13(-0.5,-9.5) AC14(0.5,-9.5) AC15(1.5,-9.5) AC16(2.5,-9.5) AC17(3.5,-9.5) AC18(4.5,-9.5) AC19(5.5,-9.5) AC20(6.5,-9.5) AC21(7.5,-9.5) AC22(8.5,-9.5) AC23(9.5,-9.5) AC24(10.5,-9.5) AC25(11.5,-9.5) AC26(12.5,-9.5) AD1(-12.5,-10.5) AD2(-11.5,-10.5) AD3(-10.5,-10.5) AD4(-9.5,-10.5) AD5(-8.5,-10.5) AD6(-7.5,-10.5) AD7(-6.5,-10.5) AD8(-5.5,-10.5) AD9(-4.5,-10.5) AD10(-3.5,-10.5) AD11(-2.5,-10.5) AD12(-1.5,-10.5) AD13(-0.5,-10.5) AD14(0.5,-10.5) AD15(1.5,-10.5) AD16(2.5,-10.5) AD17(3.5,-10.5) AD18(4.5,-10.5) AD19(5.5,-10.5) AD20(6.5,-10.5) AD21(7.5,-10.5) AD22(8.5,-10.5) AD23(9.5,-10.5) AD24(10.5,-10.5) AD25(11.5,-10.5) AD26(12.5,-10.5) AE1(-12.5,-11.5) AE2(-11.5,-11.5) AE3(-10.5,-11.5) AE4(-9.5,-11.5) AE5(-8.5,-11.5) AE6(-7.5,-11.5) AE7(-6.5,-11.5) AE8(-5.5,-11.5) AE9(-4.5,-11.5) AE10(-3.5,-11.5) AE11(-2.5,-11.5) AE12(-1.5,-11.5) AE13(-0.5,-11.5) AE14(0.5,-11.5) AE15(1.5,-11.5) AE16(2.5,-11.5) AE17(3.5,-11.5) AE18(4.5,-11.5) AE19(5.5,-11.5) AE20(6.5,-11.5) AE21(7.5,-11.5) AE22(8.5,-11.5) AE23(9.5,-11.5) AE24(10.5,-11.5) AE25(11.5,-11.5) AE26(12.5,-11.5) AF1(-12.5,-12.5) AF2(-11.5,-12.5) AF3(-10.5,-12.5) AF4(-9.5,-12.5) AF5(-8.5,-12.5) AF6(-7.5,-12.5) AF7(-6.5,-12.5) AF8(-5.5,-12.5) AF9(-4.5,-12.5) AF10(-3.5,-12.5) AF11(-2.5,-12.5) AF12(-1.5,-12.5) AF13(-0.5,-12.5) AF14(0.5,-12.5) AF15(1.5,-12.5) AF16(2.5,-12.5) AF17(3.5,-12.5) AF18(4.5,-12.5) AF19(5.5,-12.5) AF20(6.5,-12.5) AF21(7.5,-12.5) AF22(8.5,-12.5) AF23(9.5,-12.5) AF24(10.5,-12.5) AF25(11.5,-12.5) AF26(12.5,-12.5) B1(-12.5,11.5) B2(-11.5,11.5) B3(-10.5,11.5) B4(-9.5,11.5) B5(-8.5,11.5) B6(-7.5,11.5) B7(-6.5,11.5) B8(-5.5,11.5) B9(-4.5,11.5) B10(-3.5,11.5) B11(-2.5,11.5) B12(-1.5,11.5) B13(-0.5,11.5) B14(0.5,11.5) B15(1.5,11.5) B16(2.5,11.5) B17(3.5,11.5) B18(4.5,11.5) B19(5.5,11.5) B20(6.5,11.5) B21(7.5,11.5) B22(8.5,11.5) B23(9.5,11.5) B24(10.5,11.5) B25(11.5,11.5) B26(12.5,11.5) C1(-12.5,10.5) C2(-11.5,10.5) C3(-10.5,10.5) C4(-9.5,10.5) C5(-8.5,10.5) C6(-7.5,10.5) C7(-6.5,10.5) C8(-5.5,10.5) C9(-4.5,10.5) C10(-3.5,10.5) C11(-2.5,10.5) C12(-1.5,10.5) C13(-0.5,10.5) C14(0.5,10.5) C15(1.5,10.5) C16(2.5,10.5) C17(3.5,10.5) C18(4.5,10.5) C19(5.5,10.5) C20(6.5,10.5) C21(7.5,10.5) C22(8.5,10.5) C23(9.5,10.5) C24(10.5,10.5) C25(11.5,10.5) C26(12.5,10.5) D1(-12.5,9.5) D2(-11.5,9.5) D3(-10.5,9.5) D4(-9.5,9.5) D5(-8.5,9.5) D6(-7.5,9.5) D7(-6.5,9.5) D8(-5.5,9.5) D9(-4.5,9.5) D10(-3.5,9.5) D11(-2.5,9.5) D12(-1.5,9.5) D13(-0.5,9.5) D14(0.5,9.5) D15(1.5,9.5) D16(2.5,9.5) D17(3.5,9.5) D18(4.5,9.5) D19(5.5,9.5) D20(6.5,9.5) D21(7.5,9.5) D22(8.5,9.5) D23(9.5,9.5) D24(10.5,9.5) D25(11.5,9.5) D26(12.5,9.5) E1(-12.5,8.5) E2(-11.5,8.5) E3(-10.5,8.5) E4(-9.5,8.5) E5(-8.5,8.5) E6(-7.5,8.5) E7(-6.5,8.5) E8(-5.5,8.5) E9(-4.5,8.5) E10(-3.5,8.5) E11(-2.5,8.5) E12(-1.5,8.5) E13(-0.5,8.5) E14(0.5,8.5) E15(1.5,8.5) E16(2.5,8.5) E17(3.5,8.5) E18(4.5,8.5) E19(5.5,8.5) E20(6.5,8.5) E21(7.5,8.5) E22(8.5,8.5) E23(9.5,8.5) E24(10.5,8.5) E25(11.5,8.5) E26(12.5,8.5) F1(-12.5,7.5) F2(-11.5,7.5) F3(-10.5,7.5) F4(-9.5,7.5) F5(-8.5,7.5) F6(-7.5,7.5) F7(-6.5,7.5) F8(-5.5,7.5) F9(-4.5,7.5) F10(-3.5,7.5) F11(-2.5,7.5) F12(-1.5,7.5) F13(-0.5,7.5) F14(0.5,7.5) F15(1.5,7.5) F16(2.5,7.5) F17(3.5,7.5) F18(4.5,7.5) F19(5.5,7.5) F20(6.5,7.5) F21(7.5,7.5) F22(8.5,7.5) F23(9.5,7.5) F24(10.5,7.5) F25(11.5,7.5) F26(12.5,7.5) G1(-12.5,6.5) G2(-11.5,6.5) G3(-10.5,6.5) G4(-9.5,6.5) G5(-8.5,6.5) G6(-7.5,6.5) G7(-6.5,6.5) G8(-5.5,6.5) G9(-4.5,6.5) G10(-3.5,6.5) G11(-2.5,6.5) G12(-1.5,6.5) G13(-0.5,6.5) G14(0.5,6.5) G15(1.5,6.5) G16(2.5,6.5) G17(3.5,6.5) G18(4.5,6.5) G19(5.5,6.5) G20(6.5,6.5) G21(7.5,6.5) G22(8.5,6.5) G23(9.5,6.5) G24(10.5,6.5) G25(11.5,6.5) G26(12.5,6.5) H1(-12.5,5.5) H2(-11.5,5.5) H3(-10.5,5.5) H4(-9.5,5.5) H5(-8.5,5.5) H6(-7.5,5.5) H7(-6.5,5.5) H8(-5.5,5.5) H9(-4.5,5.5) H10(-3.5,5.5) H11(-2.5,5.5) H12(-1.5,5.5) H13(-0.5,5.5) H14(0.5,5.5) H15(1.5,5.5) H16(2.5,5.5) H17(3.5,5.5) H18(4.5,5.5) H19(5.5,5.5) H20(6.5,5.5) H21(7.5,5.5) H22(8.5,5.5) H23(9.5,5.5) H24(10.5,5.5) H25(11.5,5.5) H26(12.5,5.5) J1(-12.5,4.5) J2(-11.5,4.5) J3(-10.5,4.5) J4(-9.5,4.5) J5(-8.5,4.5) J6(-7.5,4.5) J7(-6.5,4.5) J8(-5.5,4.5) J9(-4.5,4.5) J10(-3.5,4.5) J11(-2.5,4.5) J12(-1.5,4.5) J13(-0.5,4.5) J14(0.5,4.5) J15(1.5,4.5) J16(2.5,4.5) J17(3.5,4.5) J18(4.5,4.5) J19(5.5,4.5) J20(6.5,4.5) J21(7.5,4.5) J22(8.5,4.5) J23(9.5,4.5) J24(10.5,4.5) J25(11.5,4.5) J26(12.5,4.5) K1(-12.5,3.5) K2(-11.5,3.5) K3(-10.5,3.5) K4(-9.5,3.5) K5(-8.5,3.5) K6(-7.5,3.5) K7(-6.5,3.5) K8(-5.5,3.5) K9(-4.5,3.5) K10(-3.5,3.5) K11(-2.5,3.5) K12(-1.5,3.5) K13(-0.5,3.5) K14(0.5,3.5) K15(1.5,3.5) K16(2.5,3.5) K17(3.5,3.5) K18(4.5,3.5) K19(5.5,3.5) K20(6.5,3.5) K21(7.5,3.5) K22(8.5,3.5) K23(9.5,3.5) K24(10.5,3.5) K25(11.5,3.5) K26(12.5,3.5) L1(-12.5,2.5) L2(-11.5,2.5) L3(-10.5,2.5) L4(-9.5,2.5) L5(-8.5,2.5) L6(-7.5,2.5) L7(-6.5,2.5) L8(-5.5,2.5) L9(-4.5,2.5) L10(-3.5,2.5) L11(-2.5,2.5) L12(-1.5,2.5) L13(-0.5,2.5) L14(0.5,2.5) L15(1.5,2.5) L16(2.5,2.5) L17(3.5,2.5) L18(4.5,2.5) L19(5.5,2.5) L20(6.5,2.5) L21(7.5,2.5) L22(8.5,2.5) L23(9.5,2.5) L24(10.5,2.5) L25(11.5,2.5) L26(12.5,2.5) M1(-12.5,1.5) M2(-11.5,1.5) M3(-10.5,1.5) M4(-9.5,1.5) M5(-8.5,1.5) M6(-7.5,1.5) M7(-6.5,1.5) M8(-5.5,1.5) M9(-4.5,1.5) M10(-3.5,1.5) M11(-2.5,1.5) M12(-1.5,1.5) M13(-0.5,1.5) M14(0.5,1.5) M15(1.5,1.5) M16(2.5,1.5) M17(3.5,1.5) M18(4.5,1.5) M19(5.5,1.5) M20(6.5,1.5) M21(7.5,1.5) M22(8.5,1.5) M23(9.5,1.5) M24(10.5,1.5) M25(11.5,1.5) M26(12.5,1.5) N1(-12.5,0.5) N2(-11.5,0.5) N3(-10.5,0.5) N4(-9.5,0.5) N5(-8.5,0.5) N6(-7.5,0.5) N7(-6.5,0.5) N8(-5.5,0.5) N9(-4.5,0.5) N10(-3.5,0.5) N11(-2.5,0.5) N12(-1.5,0.5) N13(-0.5,0.5) N14(0.5,0.5) N15(1.5,0.5) N16(2.5,0.5) N17(3.5,0.5) N18(4.5,0.5) N19(5.5,0.5) N20(6.5,0.5) N21(7.5,0.5) N22(8.5,0.5) N23(9.5,0.5) N24(10.5,0.5) N25(11.5,0.5) N26(12.5,0.5) P1(-12.5,-0.5) P2(-11.5,-0.5) P3(-10.5,-0.5) P4(-9.5,-0.5) P5(-8.5,-0.5) P6(-7.5,-0.5) P7(-6.5,-0.5) P8(-5.5,-0.5) P9(-4.5,-0.5) P10(-3.5,-0.5) P11(-2.5,-0.5) P12(-1.5,-0.5) P13(-0.5,-0.5) P14(0.5,-0.5) P15(1.5,-0.5) P16(2.5,-0.5) P17(3.5,-0.5) P18(4.5,-0.5) P19(5.5,-0.5) P20(6.5,-0.5) P21(7.5,-0.5) P22(8.5,-0.5) P23(9.5,-0.5) P24(10.5,-0.5) P25(11.5,-0.5) P26(12.5,-0.5) R1(-12.5,-1.5) R2(-11.5,-1.5) R3(-10.5,-1.5) R4(-9.5,-1.5) R5(-8.5,-1.5) R6(-7.5,-1.5) R7(-6.5,-1.5) R8(-5.5,-1.5) R9(-4.5,-1.5) R10(-3.5,-1.5) R11(-2.5,-1.5) R12(-1.5,-1.5) R13(-0.5,-1.5) R14(0.5,-1.5) R15(1.5,-1.5) R16(2.5,-1.5) R17(3.5,-1.5) R18(4.5,-1.5) R19(5.5,-1.5) R20(6.5,-1.5) R21(7.5,-1.5) R22(8.5,-1.5) R23(9.5,-1.5) R24(10.5,-1.5) R25(11.5,-1.5) R26(12.5,-1.5) T1(-12.5,-2.5) T2(-11.5,-2.5) T3(-10.5,-2.5) T4(-9.5,-2.5) T5(-8.5,-2.5) T6(-7.5,-2.5) T7(-6.5,-2.5) T8(-5.5,-2.5) T9(-4.5,-2.5) T10(-3.5,-2.5) T11(-2.5,-2.5) T12(-1.5,-2.5) T13(-0.5,-2.5) T14(0.5,-2.5) T15(1.5,-2.5) T16(2.5,-2.5) T17(3.5,-2.5) T18(4.5,-2.5) T19(5.5,-2.5) T20(6.5,-2.5) T21(7.5,-2.5) T22(8.5,-2.5) T23(9.5,-2.5) T24(10.5,-2.5) T25(11.5,-2.5) T26(12.5,-2.5) U1(-12.5,-3.5) U2(-11.5,-3.5) U3(-10.5,-3.5) U4(-9.5,-3.5) U5(-8.5,-3.5) U6(-7.5,-3.5) U7(-6.5,-3.5) U8(-5.5,-3.5) U9(-4.5,-3.5) U10(-3.5,-3.5) U11(-2.5,-3.5) U12(-1.5,-3.5) U13(-0.5,-3.5) U14(0.5,-3.5) U15(1.5,-3.5) U16(2.5,-3.5) U17(3.5,-3.5) U18(4.5,-3.5) U19(5.5,-3.5) U20(6.5,-3.5) U21(7.5,-3.5) U22(8.5,-3.5) U23(9.5,-3.5) U24(10.5,-3.5) U25(11.5,-3.5) U26(12.5,-3.5) V1(-12.5,-4.5) V2(-11.5,-4.5) V3(-10.5,-4.5) V4(-9.5,-4.5) V5(-8.5,-4.5) V6(-7.5,-4.5) V7(-6.5,-4.5) V8(-5.5,-4.5) V9(-4.5,-4.5) V10(-3.5,-4.5) V11(-2.5,-4.5) V12(-1.5,-4.5) V13(-0.5,-4.5) V14(0.5,-4.5) V15(1.5,-4.5) V16(2.5,-4.5) V17(3.5,-4.5) V18(4.5,-4.5) V19(5.5,-4.5) V20(6.5,-4.5) V21(7.5,-4.5) V22(8.5,-4.5) V23(9.5,-4.5) V24(10.5,-4.5) V25(11.5,-4.5) V26(12.5,-4.5) W1(-12.5,-5.5) W2(-11.5,-5.5) W3(-10.5,-5.5) W4(-9.5,-5.5) W5(-8.5,-5.5) W6(-7.5,-5.5) W7(-6.5,-5.5) W8(-5.5,-5.5) W9(-4.5,-5.5) W10(-3.5,-5.5) W11(-2.5,-5.5) W12(-1.5,-5.5) W13(-0.5,-5.5) W14(0.5,-5.5) W15(1.5,-5.5) W16(2.5,-5.5) W17(3.5,-5.5) W18(4.5,-5.5) W19(5.5,-5.5) W20(6.5,-5.5) W21(7.5,-5.5) W22(8.5,-5.5) W23(9.5,-5.5) W24(10.5,-5.5) W25(11.5,-5.5) W26(12.5,-5.5) Y1(-12.5,-6.5) Y2(-11.5,-6.5) Y3(-10.5,-6.5) Y4(-9.5,-6.5) Y5(-8.5,-6.5) Y6(-7.5,-6.5) Y7(-6.5,-6.5) Y8(-5.5,-6.5) Y9(-4.5,-6.5) Y10(-3.5,-6.5) Y11(-2.5,-6.5) Y12(-1.5,-6.5) Y13(-0.5,-6.5) Y14(0.5,-6.5) Y15(1.5,-6.5) Y16(2.5,-6.5) Y17(3.5,-6.5) Y18(4.5,-6.5) Y19(5.5,-6.5) Y20(6.5,-6.5) Y21(7.5,-6.5) Y22(8.5,-6.5) Y23(9.5,-6.5) Y24(10.5,-6.5) Y25(11.5,-6.5) Y26(12.5,-6.5)
Top Overlay:
  circle w0.25: c-14.15,12.5 r0.125
  region: -12.5,13.5 -13.5,12.5 -13.5,13.5
  lines w0.2: -13.5,12.5 -12.5,13.5 ; -13.5,-13.5 13.5,-13.5 13.5,13.5 -13.5,13.5 -13.5,-13.5
Mechanical 13:
  lines w0.1: -13.5,-13.5 13.5,-13.5 13.5,13.5 -13.5,13.5 -13.5,-13.5
Mechanical 15:
  lines w0.1: -0.5,0 0.5,0 ; 0,-0.5 0,0.5 ; -14.5,-14.5 14.5,-14.5 14.5,14.5 -14.5,14.5 -14.5,-14.5
3D body: height 0, standoff 0, extent -13.5,-13.5 13.5,13.5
